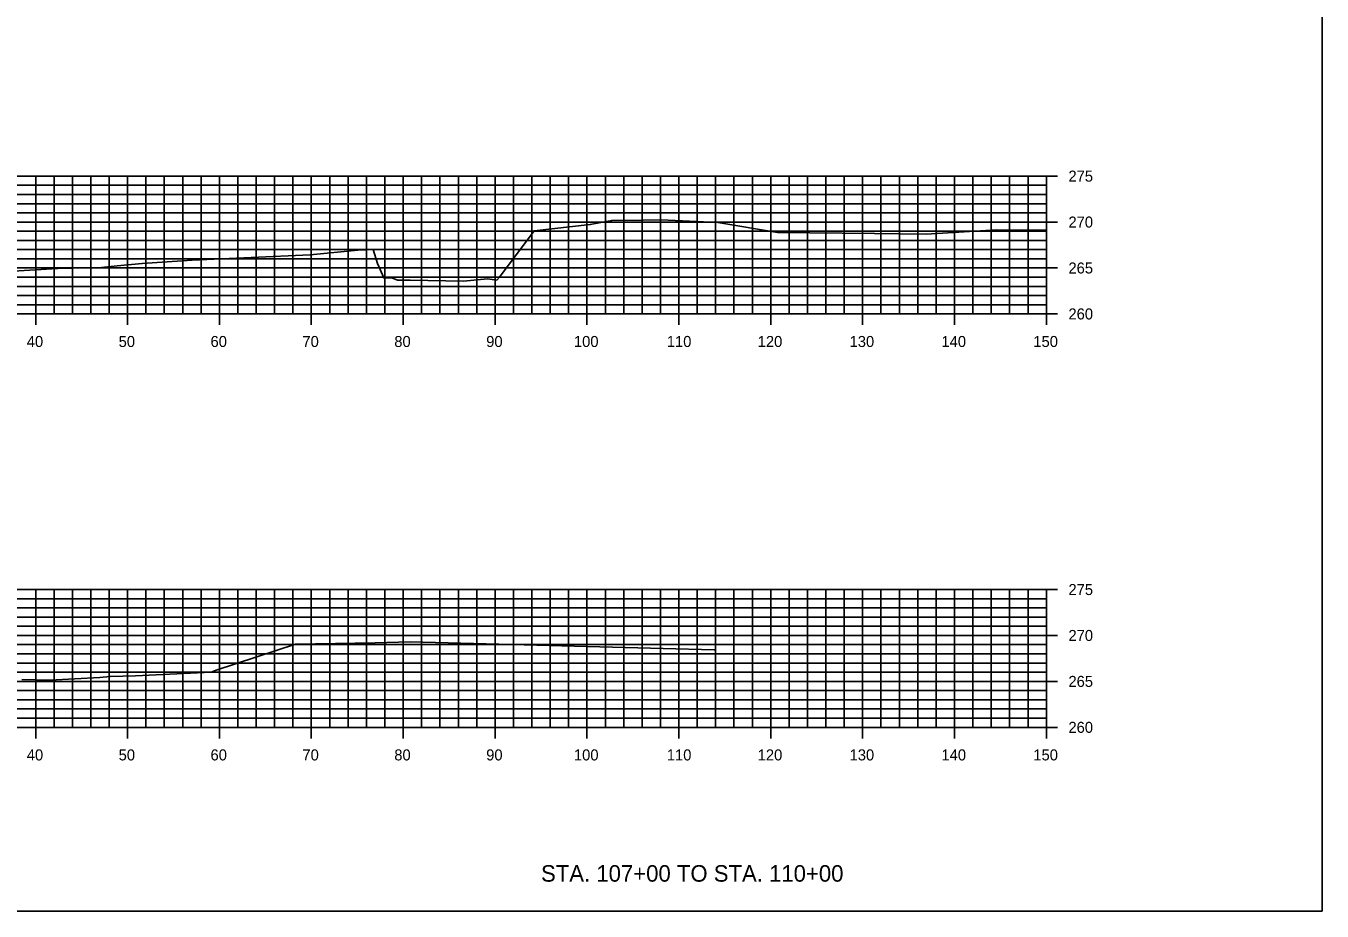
# Model space of a CAD drawing. Extents: x 1661012 to 1662122, y 670053 to 671852.
# Drawn here: x 1661230.9 to 1661372, y 671274.1 to 671370.5 of the extents above; entities that cross this region are included whole.
import ezdxf

# ---------------------------------------------------------------- set-up
doc = ezdxf.new("R2010")
doc.units = 0
for name, color, linetype in [('R_Concrete', 7, 'Continuous'), ('R_Concrete Hidden', 7, 'Continuous'), ('R_Erosion', 7, 'Continuous'), ('R_Exist Surface', 7, 'Continuous'), ('R_Proposed Road', 7, 'Continuous')]:
    doc.layers.add(name, color=color, linetype=linetype)

msp = doc.modelspace()

# ---------------------------------------------------------------- linework, layer by layer
at = {"layer": 'R_Concrete'}
for p, q in [((1661041.99, 671354.12), (1661341.99, 671354.12)), ((1661231.99, 671339.12), (1661231.99, 671354.12)), ((1661233.99, 671339.12), (1661233.99, 671354.12)), ((1661235.99, 671339.12), (1661235.99, 671354.12)), ((1661237.99, 671339.12), (1661237.99, 671354.12)), ((1661239.99, 671339.12), (1661239.99, 671354.12)), ((1661241.99, 671339.12), (1661241.99, 671354.12)), ((1661243.99, 671339.12), (1661243.99, 671354.12)), ((1661245.99, 671339.12), (1661245.99, 671354.12)), ((1661247.99, 671339.12), (1661247.99, 671354.12)), ((1661249.99, 671339.12), (1661249.99, 671354.12)), ((1661251.99, 671339.12), (1661251.99, 671354.12)), ((1661253.99, 671339.12), (1661253.99, 671354.12)), ((1661255.99, 671339.12), (1661255.99, 671354.12)), ((1661257.99, 671339.12), (1661257.99, 671354.12)), ((1661259.99, 671339.12), (1661259.99, 671354.12)), ((1661261.99, 671339.12), (1661261.99, 671354.12)), ((1661263.99, 671339.12), (1661263.99, 671354.12)), ((1661265.99, 671339.12), (1661265.99, 671354.12)), ((1661267.99, 671339.12), (1661267.99, 671354.12)), ((1661269.99, 671339.12), (1661269.99, 671354.12)), ((1661271.99, 671339.12), (1661271.99, 671354.12)), ((1661273.99, 671339.12), (1661273.99, 671354.12)), ((1661275.99, 671339.12), (1661275.99, 671354.12)), ((1661277.99, 671339.12), (1661277.99, 671354.12)), ((1661279.99, 671339.12), (1661279.99, 671354.12)), ((1661281.99, 671339.12), (1661281.99, 671354.12)), ((1661283.99, 671339.12), (1661283.99, 671354.12)), ((1661285.99, 671339.12), (1661285.99, 671354.12)), ((1661287.99, 671339.12), (1661287.99, 671354.12)), ((1661289.99, 671339.12), (1661289.99, 671354.12)), ((1661291.99, 671339.12), (1661291.99, 671354.12)), ((1661293.99, 671339.12), (1661293.99, 671354.12)), ((1661295.99, 671339.12), (1661295.99, 671354.12)), ((1661297.99, 671339.12), (1661297.99, 671354.12)), ((1661299.99, 671339.12), (1661299.99, 671354.12)), ((1661301.99, 671339.12), (1661301.99, 671354.12)), ((1661303.99, 671339.12), (1661303.99, 671354.12)), ((1661305.99, 671339.12), (1661305.99, 671354.12)), ((1661307.99, 671339.12), (1661307.99, 671354.12)), ((1661309.99, 671339.12), (1661309.99, 671354.12)), ((1661311.99, 671339.12), (1661311.99, 671354.12)), ((1661313.99, 671339.12), (1661313.99, 671354.12)), ((1661315.99, 671339.12), (1661315.99, 671354.12)), ((1661317.99, 671339.12), (1661317.99, 671354.12)), ((1661319.99, 671339.12), (1661319.99, 671354.12)), ((1661321.99, 671339.12), (1661321.99, 671354.12)), ((1661323.99, 671339.12), (1661323.99, 671354.12)), ((1661325.99, 671339.12), (1661325.99, 671354.12)), ((1661327.99, 671339.12), (1661327.99, 671354.12)), ((1661329.99, 671339.12), (1661329.99, 671354.12)), ((1661331.99, 671339.12), (1661331.99, 671354.12)), ((1661333.99, 671339.12), (1661333.99, 671354.12)), ((1661335.99, 671339.12), (1661335.99, 671354.12)), ((1661337.99, 671339.12), (1661337.99, 671354.12)), ((1661339.99, 671339.12), (1661339.99, 671354.12)), ((1661343.19, 671354.12), (1661340.79, 671354.12)), ((1661341.99, 671339.12), (1661341.99, 671354.12)), ((1661041.99, 671353.12), (1661341.99, 671353.12)), ((1661041.99, 671352.12), (1661341.99, 671352.12)), ((1661341.99, 671353.12), (1661341.39, 671353.12)), ((1661341.99, 671352.12), (1661341.39, 671352.12)), ((1661041.99, 671351.12), (1661341.99, 671351.12)), ((1661341.99, 671351.12), (1661341.39, 671351.12)), ((1661041.99, 671350.12), (1661341.99, 671350.12)), ((1661341.99, 671350.12), (1661341.39, 671350.12)), ((1661041.99, 671349.12), (1661341.99, 671349.12)), ((1661041.99, 671348.12), (1661341.99, 671348.12)), ((1661343.19, 671349.12), (1661340.79, 671349.12)), ((1661341.99, 671348.12), (1661341.39, 671348.12)), ((1661041.99, 671347.12), (1661341.99, 671347.12)), ((1661341.99, 671347.12), (1661341.39, 671347.12)), ((1661041.99, 671346.12), (1661341.99, 671346.12)), ((1661041.99, 671345.12), (1661341.99, 671345.12)), ((1661341.99, 671346.12), (1661341.39, 671346.12)), ((1661341.99, 671345.12), (1661341.39, 671345.12)), ((1661041.99, 671344.12), (1661341.99, 671344.12)), ((1661343.19, 671344.12), (1661340.79, 671344.12)), ((1661041.99, 671343.12), (1661341.99, 671343.12)), ((1661041.99, 671342.12), (1661341.99, 671342.12)), ((1661341.99, 671343.12), (1661341.39, 671343.12)), ((1661341.99, 671342.12), (1661341.39, 671342.12)), ((1661041.99, 671341.12), (1661341.99, 671341.12)), ((1661341.99, 671341.12), (1661341.39, 671341.12)), ((1661041.99, 671340.12), (1661341.99, 671340.12)), ((1661231.99, 671337.92), (1661231.99, 671340.32)), ((1661233.99, 671339.12), (1661233.99, 671339.72)), ((1661235.99, 671339.12), (1661235.99, 671339.72)), ((1661237.99, 671339.12), (1661237.99, 671339.72)), ((1661239.99, 671339.12), (1661239.99, 671339.72)), ((1661241.99, 671337.92), (1661241.99, 671340.32)), ((1661243.99, 671339.12), (1661243.99, 671339.72)), ((1661245.99, 671339.12), (1661245.99, 671339.72)), ((1661247.99, 671339.12), (1661247.99, 671339.72)), ((1661249.99, 671339.12), (1661249.99, 671339.72)), ((1661251.99, 671337.92), (1661251.99, 671340.32)), ((1661253.99, 671339.12), (1661253.99, 671339.72)), ((1661255.99, 671339.12), (1661255.99, 671339.72)), ((1661257.99, 671339.12), (1661257.99, 671339.72)), ((1661259.99, 671339.12), (1661259.99, 671339.72)), ((1661261.99, 671337.92), (1661261.99, 671340.32)), ((1661263.99, 671339.12), (1661263.99, 671339.72)), ((1661265.99, 671339.12), (1661265.99, 671339.72)), ((1661267.99, 671339.12), (1661267.99, 671339.72)), ((1661269.99, 671339.12), (1661269.99, 671339.72)), ((1661271.99, 671337.92), (1661271.99, 671340.32)), ((1661273.99, 671339.12), (1661273.99, 671339.72)), ((1661275.99, 671339.12), (1661275.99, 671339.72)), ((1661277.99, 671339.12), (1661277.99, 671339.72)), ((1661279.99, 671339.12), (1661279.99, 671339.72)), ((1661281.99, 671337.92), (1661281.99, 671340.32)), ((1661283.99, 671339.12), (1661283.99, 671339.72)), ((1661285.99, 671339.12), (1661285.99, 671339.72)), ((1661287.99, 671339.12), (1661287.99, 671339.72)), ((1661289.99, 671339.12), (1661289.99, 671339.72)), ((1661291.99, 671337.92), (1661291.99, 671340.32)), ((1661293.99, 671339.12), (1661293.99, 671339.72)), ((1661295.99, 671339.12), (1661295.99, 671339.72)), ((1661297.99, 671339.12), (1661297.99, 671339.72)), ((1661299.99, 671339.12), (1661299.99, 671339.72)), ((1661301.99, 671337.92), (1661301.99, 671340.32)), ((1661303.99, 671339.12), (1661303.99, 671339.72)), ((1661305.99, 671339.12), (1661305.99, 671339.72)), ((1661307.99, 671339.12), (1661307.99, 671339.72)), ((1661309.99, 671339.12), (1661309.99, 671339.72)), ((1661311.99, 671337.92), (1661311.99, 671340.32)), ((1661313.99, 671339.12), (1661313.99, 671339.72)), ((1661315.99, 671339.12), (1661315.99, 671339.72)), ((1661317.99, 671339.12), (1661317.99, 671339.72)), ((1661319.99, 671339.12), (1661319.99, 671339.72)), ((1661321.99, 671337.92), (1661321.99, 671340.32)), ((1661323.99, 671339.12), (1661323.99, 671339.72)), ((1661325.99, 671339.12), (1661325.99, 671339.72)), ((1661327.99, 671339.12), (1661327.99, 671339.72)), ((1661329.99, 671339.12), (1661329.99, 671339.72)), ((1661331.99, 671337.92), (1661331.99, 671340.32)), ((1661333.99, 671339.12), (1661333.99, 671339.72)), ((1661335.99, 671339.12), (1661335.99, 671339.72)), ((1661337.99, 671339.12), (1661337.99, 671339.72)), ((1661339.99, 671339.12), (1661339.99, 671339.72)), ((1661341.99, 671340.12), (1661341.39, 671340.12)), ((1661341.99, 671337.92), (1661341.99, 671340.32)), ((1661041.99, 671339.12), (1661341.99, 671339.12)), ((1661343.19, 671339.12), (1661340.79, 671339.12)), ((1661041.99, 671309.12), (1661341.99, 671309.12)), ((1661231.99, 671294.12), (1661231.99, 671309.12)), ((1661233.99, 671294.12), (1661233.99, 671309.12)), ((1661235.99, 671294.12), (1661235.99, 671309.12)), ((1661237.99, 671294.12), (1661237.99, 671309.12)), ((1661239.99, 671294.12), (1661239.99, 671309.12)), ((1661241.99, 671294.12), (1661241.99, 671309.12)), ((1661243.99, 671294.12), (1661243.99, 671309.12)), ((1661245.99, 671294.12), (1661245.99, 671309.12)), ((1661247.99, 671294.12), (1661247.99, 671309.12)), ((1661249.99, 671294.12), (1661249.99, 671309.12)), ((1661251.99, 671294.12), (1661251.99, 671309.12)), ((1661253.99, 671294.12), (1661253.99, 671309.12)), ((1661255.99, 671294.12), (1661255.99, 671309.12)), ((1661257.99, 671294.12), (1661257.99, 671309.12)), ((1661259.99, 671294.12), (1661259.99, 671309.12)), ((1661261.99, 671294.12), (1661261.99, 671309.12)), ((1661263.99, 671294.12), (1661263.99, 671309.12)), ((1661265.99, 671294.12), (1661265.99, 671309.12)), ((1661267.99, 671294.12), (1661267.99, 671309.12)), ((1661269.99, 671294.12), (1661269.99, 671309.12)), ((1661271.99, 671294.12), (1661271.99, 671309.12)), ((1661273.99, 671294.12), (1661273.99, 671309.12)), ((1661275.99, 671294.12), (1661275.99, 671309.12)), ((1661277.99, 671294.12), (1661277.99, 671309.12)), ((1661279.99, 671294.12), (1661279.99, 671309.12)), ((1661281.99, 671294.12), (1661281.99, 671309.12)), ((1661283.99, 671294.12), (1661283.99, 671309.12)), ((1661285.99, 671294.12), (1661285.99, 671309.12)), ((1661287.99, 671294.12), (1661287.99, 671309.12)), ((1661289.99, 671294.12), (1661289.99, 671309.12)), ((1661291.99, 671294.12), (1661291.99, 671309.12)), ((1661293.99, 671294.12), (1661293.99, 671309.12)), ((1661295.99, 671294.12), (1661295.99, 671309.12)), ((1661297.99, 671294.12), (1661297.99, 671309.12)), ((1661299.99, 671294.12), (1661299.99, 671309.12)), ((1661301.99, 671294.12), (1661301.99, 671309.12)), ((1661303.99, 671294.12), (1661303.99, 671309.12)), ((1661305.99, 671294.12), (1661305.99, 671309.12)), ((1661307.99, 671294.12), (1661307.99, 671309.12)), ((1661309.99, 671294.12), (1661309.99, 671309.12)), ((1661311.99, 671294.12), (1661311.99, 671309.12)), ((1661313.99, 671294.12), (1661313.99, 671309.12)), ((1661315.99, 671294.12), (1661315.99, 671309.12)), ((1661317.99, 671294.12), (1661317.99, 671309.12)), ((1661319.99, 671294.12), (1661319.99, 671309.12)), ((1661321.99, 671294.12), (1661321.99, 671309.12)), ((1661323.99, 671294.12), (1661323.99, 671309.12)), ((1661325.99, 671294.12), (1661325.99, 671309.12)), ((1661327.99, 671294.12), (1661327.99, 671309.12)), ((1661329.99, 671294.12), (1661329.99, 671309.12)), ((1661331.99, 671294.12), (1661331.99, 671309.12)), ((1661333.99, 671294.12), (1661333.99, 671309.12)), ((1661335.99, 671294.12), (1661335.99, 671309.12)), ((1661337.99, 671294.12), (1661337.99, 671309.12)), ((1661339.99, 671294.12), (1661339.99, 671309.12)), ((1661343.19, 671309.12), (1661340.79, 671309.12)), ((1661341.99, 671294.12), (1661341.99, 671309.12)), ((1661041.99, 671308.12), (1661341.99, 671308.12)), ((1661041.99, 671307.12), (1661341.99, 671307.12)), ((1661341.99, 671308.12), (1661341.39, 671308.12)), ((1661341.99, 671307.12), (1661341.39, 671307.12)), ((1661041.99, 671306.12), (1661341.99, 671306.12)), ((1661341.99, 671306.12), (1661341.39, 671306.12)), ((1661041.99, 671305.12), (1661341.99, 671305.12)), ((1661041.99, 671304.12), (1661341.99, 671304.12)), ((1661343.19, 671304.12), (1661340.79, 671304.12)), ((1661341.99, 671305.12), (1661341.39, 671305.12)), ((1661041.99, 671303.12), (1661341.99, 671303.12)), ((1661341.99, 671303.12), (1661341.39, 671303.12)), ((1661041.99, 671302.12), (1661341.99, 671302.12)), ((1661341.99, 671302.12), (1661341.39, 671302.12)), ((1661041.99, 671301.12), (1661341.99, 671301.12)), ((1661041.99, 671300.12), (1661341.99, 671300.12)), ((1661341.99, 671301.12), (1661341.39, 671301.12)), ((1661341.99, 671300.12), (1661341.39, 671300.12)), ((1661041.99, 671299.12), (1661341.99, 671299.12)), ((1661343.19, 671299.12), (1661340.79, 671299.12)), ((1661041.99, 671298.12), (1661341.99, 671298.12)), ((1661041.99, 671297.12), (1661341.99, 671297.12)), ((1661341.99, 671298.12), (1661341.39, 671298.12)), ((1661341.99, 671297.12), (1661341.39, 671297.12)), ((1661041.99, 671296.12), (1661341.99, 671296.12)), ((1661341.99, 671296.12), (1661341.39, 671296.12)), ((1661041.99, 671295.12), (1661341.99, 671295.12)), ((1661231.99, 671292.92), (1661231.99, 671295.32)), ((1661233.99, 671294.12), (1661233.99, 671294.72)), ((1661235.99, 671294.12), (1661235.99, 671294.72)), ((1661237.99, 671294.12), (1661237.99, 671294.72)), ((1661239.99, 671294.12), (1661239.99, 671294.72)), ((1661241.99, 671292.92), (1661241.99, 671295.32)), ((1661243.99, 671294.12), (1661243.99, 671294.72)), ((1661245.99, 671294.12), (1661245.99, 671294.72)), ((1661247.99, 671294.12), (1661247.99, 671294.72)), ((1661249.99, 671294.12), (1661249.99, 671294.72)), ((1661251.99, 671292.92), (1661251.99, 671295.32)), ((1661253.99, 671294.12), (1661253.99, 671294.72)), ((1661255.99, 671294.12), (1661255.99, 671294.72)), ((1661257.99, 671294.12), (1661257.99, 671294.72)), ((1661259.99, 671294.12), (1661259.99, 671294.72)), ((1661261.99, 671292.92), (1661261.99, 671295.32)), ((1661263.99, 671294.12), (1661263.99, 671294.72)), ((1661265.99, 671294.12), (1661265.99, 671294.72)), ((1661267.99, 671294.12), (1661267.99, 671294.72)), ((1661269.99, 671294.12), (1661269.99, 671294.72)), ((1661271.99, 671292.92), (1661271.99, 671295.32)), ((1661273.99, 671294.12), (1661273.99, 671294.72)), ((1661275.99, 671294.12), (1661275.99, 671294.72)), ((1661277.99, 671294.12), (1661277.99, 671294.72)), ((1661279.99, 671294.12), (1661279.99, 671294.72)), ((1661281.99, 671292.92), (1661281.99, 671295.32)), ((1661283.99, 671294.12), (1661283.99, 671294.72)), ((1661285.99, 671294.12), (1661285.99, 671294.72)), ((1661287.99, 671294.12), (1661287.99, 671294.72)), ((1661289.99, 671294.12), (1661289.99, 671294.72)), ((1661291.99, 671292.92), (1661291.99, 671295.32)), ((1661293.99, 671294.12), (1661293.99, 671294.72)), ((1661295.99, 671294.12), (1661295.99, 671294.72)), ((1661297.99, 671294.12), (1661297.99, 671294.72)), ((1661299.99, 671294.12), (1661299.99, 671294.72)), ((1661301.99, 671292.92), (1661301.99, 671295.32)), ((1661303.99, 671294.12), (1661303.99, 671294.72)), ((1661305.99, 671294.12), (1661305.99, 671294.72)), ((1661307.99, 671294.12), (1661307.99, 671294.72)), ((1661309.99, 671294.12), (1661309.99, 671294.72)), ((1661311.99, 671292.92), (1661311.99, 671295.32)), ((1661313.99, 671294.12), (1661313.99, 671294.72)), ((1661315.99, 671294.12), (1661315.99, 671294.72)), ((1661317.99, 671294.12), (1661317.99, 671294.72)), ((1661319.99, 671294.12), (1661319.99, 671294.72)), ((1661321.99, 671292.92), (1661321.99, 671295.32)), ((1661323.99, 671294.12), (1661323.99, 671294.72)), ((1661325.99, 671294.12), (1661325.99, 671294.72)), ((1661327.99, 671294.12), (1661327.99, 671294.72)), ((1661329.99, 671294.12), (1661329.99, 671294.72)), ((1661331.99, 671292.92), (1661331.99, 671295.32)), ((1661333.99, 671294.12), (1661333.99, 671294.72)), ((1661335.99, 671294.12), (1661335.99, 671294.72)), ((1661337.99, 671294.12), (1661337.99, 671294.72)), ((1661339.99, 671294.12), (1661339.99, 671294.72)), ((1661341.99, 671295.12), (1661341.39, 671295.12)), ((1661341.99, 671292.92), (1661341.99, 671295.32)), ((1661041.99, 671294.12), (1661341.99, 671294.12)), ((1661343.19, 671294.12), (1661340.79, 671294.12))]:
    msp.add_line(p, q, dxfattribs=at)
at = {"layer": 'R_Erosion'}
for points in [[(1661227.08, 671343.62), (1661233.77, 671344.03), (1661234.2, 671344.06), (1661234.42, 671344.07), (1661239.14, 671344.17), (1661240.86, 671344.35), (1661243.57, 671344.6), (1661249.01, 671344.96), (1661261.85, 671345.54), (1661267.04, 671346.07), (1661268.71, 671346.14), (1661269.21, 671344.61), (1661269.87, 671343.04), (1661270.82, 671343.02), (1661271.13, 671342.9), (1661271.38, 671342.78), (1661272.75, 671342.79), (1661278.54, 671342.68), (1661281.17, 671342.94), (1661282.17, 671342.79), (1661282.46, 671343.11), (1661286.23, 671348.17), (1661292.35, 671348.85), (1661294.68, 671349.29), (1661298.11, 671349.31), (1661300.08, 671349.36), (1661306.22, 671349.09), (1661312.74, 671348), (1661323.3, 671347.86), (1661328.89, 671347.81), (1661336.6, 671348.26), (1661341.99, 671348.23)], [(1661230.5, 671299.31), (1661233.53, 671299.27), (1661238.98, 671299.55), (1661240.11, 671299.64), (1661242.86, 671299.74), (1661251.09, 671300.14), (1661251.63, 671300.33), (1661260.27, 671303.19), (1661268.93, 671303.33), (1661272.73, 671303.42), (1661300.3, 671302.7), (1661305.84, 671302.54), (1661305.94, 671302.55)]]:
    msp.add_lwpolyline(points, dxfattribs=at)
at = {"layer": 'R_Exist Surface'}
for p, q in [((1661341.99, 671339.12), (1661341.99, 671354.12)), ((1661041.99, 671339.12), (1661341.99, 671339.12)), ((1661341.99, 671294.12), (1661341.99, 671309.12)), ((1661041.99, 671294.12), (1661341.99, 671294.12))]:
    msp.add_line(p, q, dxfattribs=at)
at = {"layer": 'R_Proposed Road'}
msp.add_lwpolyline([(1661011.99, 671274.12), (1661371.99, 671274.12), (1661371.99, 671466.82), (1661011.99, 671466.82)], close=True, dxfattribs=at)

# ---------------------------------------------------------------- texts
at = {"layer": 'R_Concrete Hidden'}
for s, height, p in [('275', 1.2, (1661344.39, 671353.52)), ('270', 1.2, (1661344.39, 671348.52)), ('265', 1.2, (1661344.39, 671343.52)), ('260', 1.2, (1661344.39, 671338.52)), ('40', 1.2, (1661231.02, 671335.52)), ('50', 1.2, (1661241.02, 671335.52)), ('60', 1.2, (1661251.02, 671335.52)), ('70', 1.2, (1661261.02, 671335.52)), ('80', 1.2, (1661271.02, 671335.52)), ('90', 1.2, (1661281.02, 671335.52)), ('100', 1.2, (1661290.57, 671335.52)), ('110', 1.2, (1661300.68, 671335.52)), ('120', 1.2, (1661310.57, 671335.52)), ('130', 1.2, (1661320.57, 671335.52)), ('140', 1.2, (1661330.57, 671335.52)), ('150', 1.2, (1661340.57, 671335.52)), ('275', 1.2, (1661344.39, 671308.52)), ('270', 1.2, (1661344.39, 671303.52)), ('265', 1.2, (1661344.39, 671298.52)), ('260', 1.2, (1661344.39, 671293.52)), ('40', 1.2, (1661231.02, 671290.52)), ('50', 1.2, (1661241.02, 671290.52)), ('60', 1.2, (1661251.02, 671290.52)), ('70', 1.2, (1661261.02, 671290.52)), ('80', 1.2, (1661271.02, 671290.52)), ('90', 1.2, (1661281.02, 671290.52)), ('100', 1.2, (1661290.57, 671290.52)), ('110', 1.2, (1661300.68, 671290.52)), ('120', 1.2, (1661310.57, 671290.52)), ('130', 1.2, (1661320.57, 671290.52)), ('140', 1.2, (1661330.57, 671290.52)), ('150', 1.2, (1661340.57, 671290.52)), ('STA. 107+00 TO STA. 110+00', 1.8, (1661286.99, 671277.32))]:
    msp.add_text(s, height=height, dxfattribs=at).set_placement(p)

doc.saveas('drawing.dxf')
